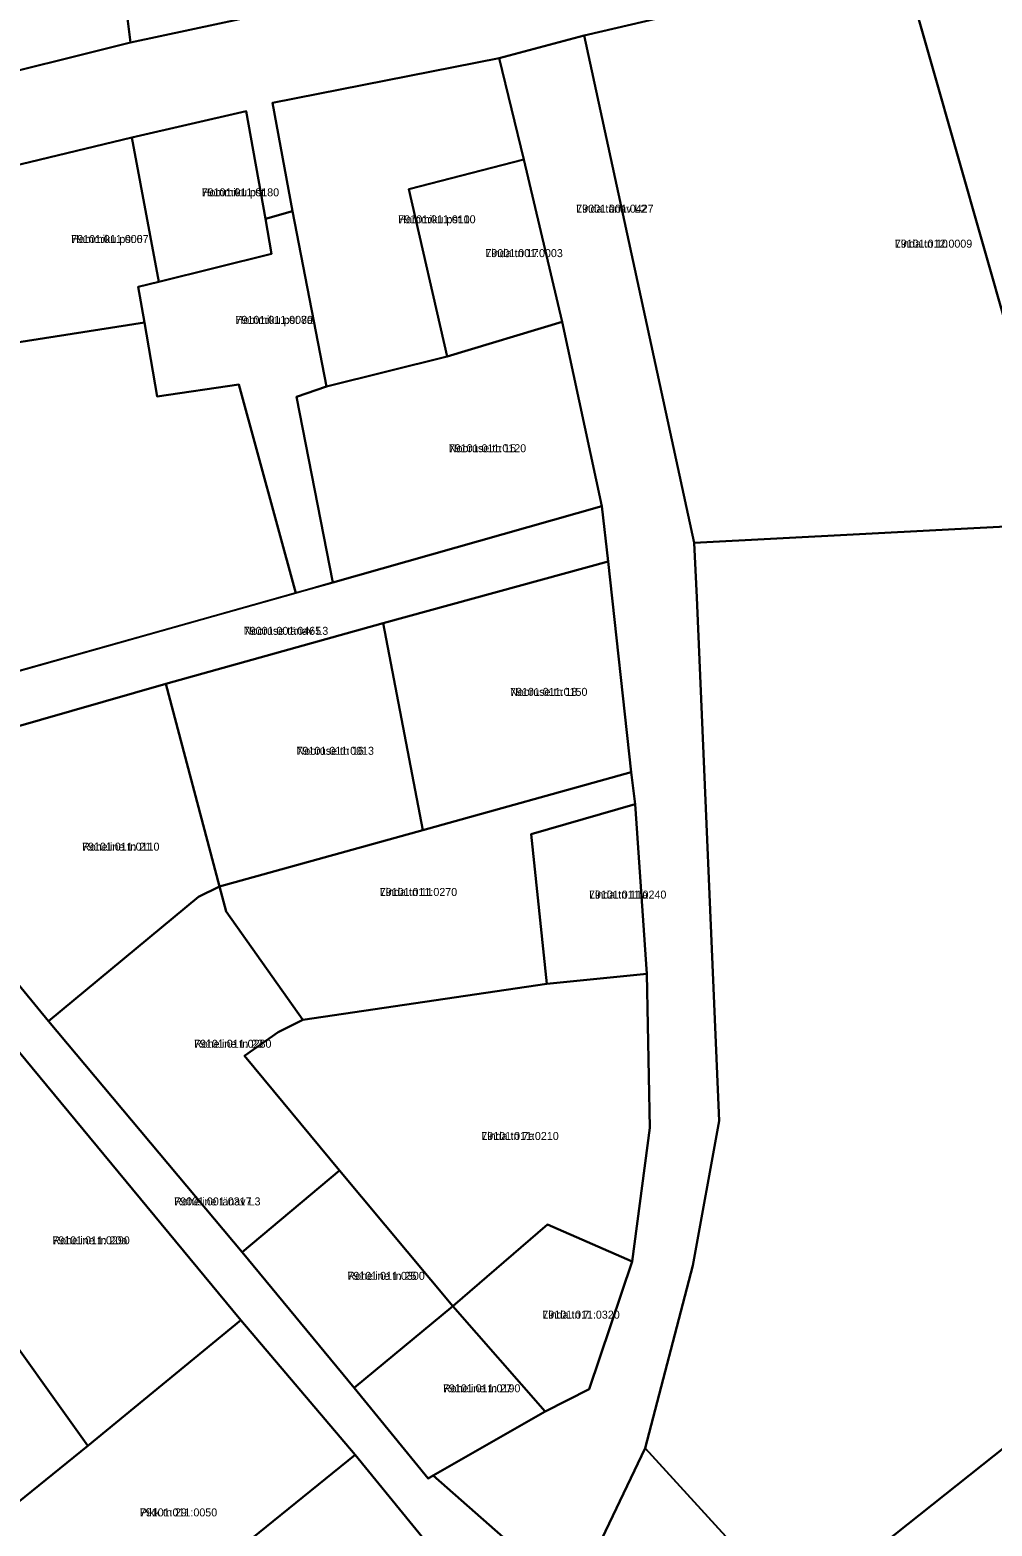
# Model space of a CAD drawing. Extents: x 587616 to 632239, y 6547421 to 6574977.
# Drawn here: x 612148.7 to 612329, y 6570710.7 to 6570991.1 of the extents above; entities that cross this region are included whole.
import ezdxf

# ---------------------------------------------------------------- set-up
doc = ezdxf.new("R2010")
doc.units = 0
for name, color, linetype in [('L_AADRESS', 7, 'Continuous'), ('PIIR', 7, 'Continuous'), ('TUNNUS', 7, 'Continuous')]:
    doc.layers.add(name, color=color, linetype=linetype)

msp = doc.modelspace()

# ---------------------------------------------------------------- linework, layer by layer
at = {"layer": 'PIIR'}
for points in [[(612196.37, 6571024.61), (612200.02, 6570995.72), (612167.56, 6570988.8), (612162.16, 6571031.85), (612195.17, 6571034.75)], [(612130.2, 6571029.46), (612160.19, 6571031.69), (612162.16, 6571031.85), (612167.56, 6570988.8), (612135.94, 6570980.88)], [(612361.85, 6570938.43), (612332.07, 6570934.19), (612312.85, 6571001.74), (612339.92, 6571007.58)], [(612252.57, 6570990.08), (612312.2, 6571004.01), (612312.85, 6571001.74), (612332.07, 6570934.19), (612361.85, 6570938.43), (612368.95, 6570920.7), (612341.84, 6570904.87), (612335.14, 6570898.25), (612273.14, 6570894.97)], [(612241.25, 6570966.88), (612236.63, 6570985.87), (612252.57, 6570990.08), (612273.14, 6570894.97), (612273.67, 6570884.71), (612277.84, 6570786.63), (612272.88, 6570759.5), (612263.99, 6570725.29), (612250.49, 6570697.01), (612224.28, 6570720.14), (612245.23, 6570732.13), (612253.5, 6570736.3), (612261.52, 6570760.26), (612264.87, 6570785.34), (612264.29, 6570814.19), (612262.13, 6570845.99), (612261.37, 6570851.97), (612257.04, 6570891.49), (612255.86, 6570901.85), (612248.4, 6570936.4)], [(612236.63, 6570985.87), (612241.25, 6570966.88), (612219.7, 6570961.26), (612226.86, 6570929.94), (612204.27, 6570924.28), (612197.91, 6570957.18), (612194.18, 6570977.5)], [(612167.79, 6570970.98), (612189.21, 6570975.91), (612192.82, 6570955.73), (612193.99, 6570949.16), (612172.88, 6570943.93)], [(612139.98, 6570964.26), (612167.79, 6570970.98), (612172.88, 6570943.93), (612169.01, 6570942.98), (612170.16, 6570936.29), (612145.09, 6570932.38)], [(612241.25, 6570966.88), (612248.4, 6570936.4), (612226.86, 6570929.94), (612219.7, 6570961.26)], [(612115.73, 6570956.18), (612139.98, 6570964.26), (612145.09, 6570932.38), (612170.16, 6570936.29), (612172.55, 6570922.42), (612187.83, 6570924.69), (612198.53, 6570885.57), (612120.26, 6570863.58), (612117.59, 6570863.28), (612104.44, 6570881.01), (612129.46, 6570900.09), (612112.59, 6570922.06), (612087.86, 6570902.98), (612063.57, 6570936.18)], [(612170.16, 6570936.29), (612169.01, 6570942.98), (612172.88, 6570943.93), (612193.99, 6570949.16), (612192.82, 6570955.73), (612197.91, 6570957.18), (612204.27, 6570924.28), (612198.65, 6570922.36), (612205.46, 6570887.54), (612198.53, 6570885.57), (612187.83, 6570924.69), (612172.55, 6570922.42)], [(612198.65, 6570922.36), (612204.27, 6570924.28), (612226.86, 6570929.94), (612248.4, 6570936.4), (612255.86, 6570901.85), (612205.46, 6570887.54)], [(612205.46, 6570887.54), (612255.86, 6570901.85), (612257.04, 6570891.49), (612214.91, 6570879.94), (612174.17, 6570868.54), (612133.01, 6570856.76), (612123.43, 6570853.62), (612117.59, 6570863.28), (612120.26, 6570863.58), (612198.47, 6570885.62)], [(612335.14, 6570898.25), (612399.71, 6570818.48), (612398.97, 6570812.81), (612384.99, 6570799.78), (612401.38, 6570781.15), (612292.21, 6570694.33), (612263.99, 6570725.29), (612272.88, 6570759.5), (612277.84, 6570786.63), (612273.67, 6570884.71), (612273.14, 6570894.97)], [(612261.37, 6570851.97), (612222.35, 6570841.11), (612214.91, 6570879.94), (612257.04, 6570891.49)], [(612184.19, 6570830.55), (612174.17, 6570868.54), (612214.91, 6570879.94), (612222.35, 6570841.11)], [(612132.75, 6570828.92), (612138.67, 6570834.59), (612133.01, 6570856.76), (612174.17, 6570868.54), (612184.19, 6570830.55), (612180.28, 6570828.61), (612152.19, 6570805.29)], [(612185.48, 6570825.9), (612184.19, 6570830.55), (612222.35, 6570841.11), (612261.37, 6570851.97), (612262.13, 6570845.99), (612242.6, 6570840.38), (612245.54, 6570812.28), (612199.81, 6570805.59)], [(612242.6, 6570840.38), (612262.13, 6570845.99), (612264.29, 6570814.19), (612245.54, 6570812.28)], [(612180.28, 6570828.61), (612184.19, 6570830.55), (612185.48, 6570825.9), (612199.81, 6570805.59), (612195.2, 6570803.28), (612188.93, 6570798.82), (612206.72, 6570777.34), (612188.46, 6570761.98), (612152.19, 6570805.29)], [(612206.72, 6570777.34), (612188.93, 6570798.82), (612195.2, 6570803.28), (612199.81, 6570805.59), (612245.54, 6570812.28), (612264.29, 6570814.19), (612264.87, 6570785.34), (612261.52, 6570760.26), (612245.7, 6570767.22), (612227.91, 6570751.88)], [(612117.59, 6570781.67), (612120.84, 6570784.23), (612141.22, 6570801), (612143.73, 6570803.06), (612188.21, 6570749.24), (612159.57, 6570725.67), (612140.34, 6570752.58), (612119.26, 6570778.1)], [(612188.46, 6570761.98), (612206.72, 6570777.34), (612227.91, 6570751.88), (612209.43, 6570736.55)], [(612245.7, 6570767.22), (612261.52, 6570760.26), (612253.5, 6570736.3), (612245.23, 6570732.13), (612227.91, 6570751.88)], [(612107.97, 6570727.29), (612140.34, 6570752.58), (612159.57, 6570725.67), (612129.01, 6570701.02)], [(612227.91, 6570751.88), (612245.23, 6570732.13), (612224.28, 6570720.14), (612223.32, 6570719.58), (612209.43, 6570736.55)], [(612129.01, 6570701.02), (612159.57, 6570725.67), (612188.21, 6570749.24), (612209.63, 6570724.02), (612176.28, 6570696.99), (612149.92, 6570675.7)], [(612209.63, 6570724.02), (612231.24, 6570697.54), (612201.52, 6570667.72), (612194.49, 6570676.09), (612183.62, 6570687.4), (612176.28, 6570696.99)], [(612250.49, 6570697.01), (612263.99, 6570725.29), (612292.21, 6570694.33), (612269.61, 6570677.95)]]:
    msp.add_lwpolyline(points, close=True, dxfattribs=at)
for points in [[(612135.94, 6570980.88), (612167.56, 6570988.8), (612200.02, 6570995.72), (612222.46, 6570999.65), (612249.87, 6571006.2), (612270.36, 6571012.11), (612310.06, 6571020.62), (612312.2, 6571004.01), (612252.57, 6570990.08), (612236.63, 6570985.87), (612194.18, 6570977.5), (612197.91, 6570957.18), (612192.82, 6570955.73), (612189.21, 6570975.91), (612167.79, 6570970.98), (612139.98, 6570964.26)], [(612292.21, 6570694.33), (612401.38, 6570781.15), (612418.39, 6570797.51), (612420.6, 6570809.75), (612443.41, 6570829.72), (612466.4, 6570849), (612500.63, 6570878.04), (612506.63, 6570883.23), (612504.11, 6570886.39), (612509.02, 6570890.5), (612523.21, 6570874.23), (612536.12, 6570859.04), (612527.28, 6570854.08), (612510.65, 6570873.21), (612483.69, 6570850.19), (612467.92, 6570836.5), (612445.15, 6570816.07), (612427.61, 6570790.85), (612405.48, 6570770.79), (612386.15, 6570753.47), (612367.62, 6570730.85), (612356.6, 6570726.21), (612339.86, 6570702.31)], [(612132.75, 6570828.92), (612152.19, 6570805.29), (612188.46, 6570761.98), (612209.43, 6570736.55), (612223.32, 6570719.58), (612224.28, 6570720.14), (612250.49, 6570697.01), (612269.61, 6570677.95), (612281.6, 6570663.77), (612283.48, 6570661.56), (612298.7, 6570642.82), (612287.9, 6570637.11), (612264.01, 6570666.42), (612255.64, 6570676.46), (612231.24, 6570697.54), (612209.63, 6570724.02), (612188.21, 6570749.24), (612143.73, 6570803.06)]]:
    msp.add_lwpolyline(points, dxfattribs=at)

# ---------------------------------------------------------------- texts
at = {"layer": 'L_AADRESS'}
for s, p in [('Hommiku pst 8', (612180.89, 6570959.95)), ('Hommiku pst 10', (612217.71, 6570954.89)), ('Linda tänav L2', (612251.06, 6570956.88)), ('Hommiku pst 6', (612156.43, 6570951.19)), ('Linda tn 10', (612310.76, 6570950.32)), ('Linda tn 17', (612234.05, 6570948.55)), ('Hommiku pst 8a', (612187.23, 6570936.04)), ('Nooruse tn 15', (612227.18, 6570911.97)), ('Nooruse tänav L3', (612188.76, 6570877.74)), ('Nooruse tn 18', (612238.66, 6570866.3)), ('Nooruse tn 16', (612198.66, 6570855.25)), ('Roheline tn 21', (612158.47, 6570837.28)), ('Linda tn 11', (612214.25, 6570828.78)), ('Linda tn 11a', (612253.45, 6570828.29)), ('Roheline tn 23', (612179.45, 6570800.33)), ('Linda tn 7a', (612233.28, 6570783.04)), ('Roheline tänav L3', (612175.73, 6570770.77)), ('Roheline tn 20a', (612152.9, 6570763.48)), ('Roheline tn 25', (612208.18, 6570756.82)), ('Linda tn 7', (612244.71, 6570749.54)), ('Roheline tn 27', (612226.09, 6570735.73)), ('Pikk tn 29', (612169.29, 6570712.47))]:
    msp.add_text(s, height=1.5, dxfattribs=at).set_placement(p)
at = {"layer": 'TUNNUS'}
for s, p in [('79101:011:0180', (612180.89, 6570959.95)), ('79101:011:0100', (612217.71, 6570954.89)), ('79001:001:0427', (612251.06, 6570956.88)), ('79101:011:0007', (612156.43, 6570951.19)), ('79101:012:0009', (612310.76, 6570950.32)), ('79001:001:0003', (612234.05, 6570948.55)), ('79101:011:0070', (612187.23, 6570936.04)), ('79101:011:0120', (612227.18, 6570911.97)), ('79001:001:0465', (612188.76, 6570877.74)), ('79101:011:0150', (612238.66, 6570866.3)), ('79101:011:0013', (612198.66, 6570855.25)), ('79101:011:0110', (612158.47, 6570837.28)), ('79101:011:0270', (612214.25, 6570828.78)), ('79101:011:0240', (612253.45, 6570828.29)), ('79101:011:0280', (612179.45, 6570800.33)), ('79101:011:0210', (612233.28, 6570783.04)), ('79001:001:0317', (612175.73, 6570770.77)), ('79101:011:0290', (612152.9, 6570763.48)), ('79101:011:0300', (612208.18, 6570756.82)), ('79101:011:0320', (612244.71, 6570749.54)), ('79101:011:0190', (612226.09, 6570735.73)), ('79101:011:0050', (612169.29, 6570712.47))]:
    msp.add_text(s, height=1.5, dxfattribs=at).set_placement(p)

doc.saveas('drawing.dxf')
